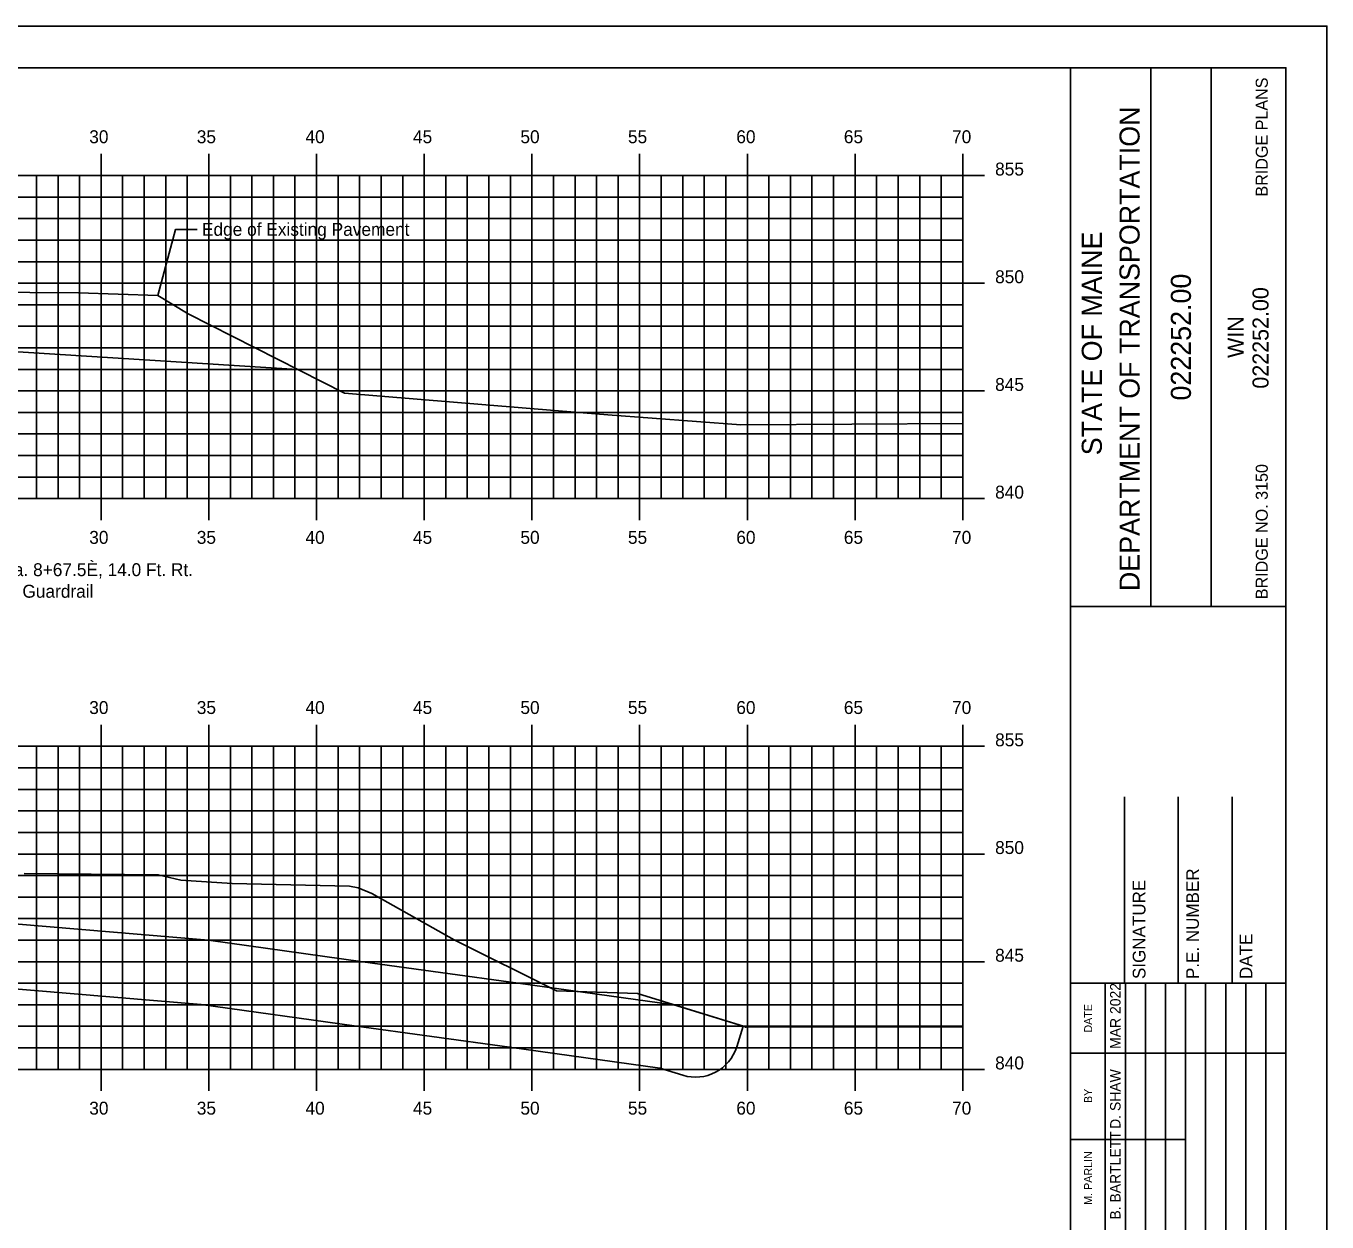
# Model space of a CAD drawing. Extents: x 2194256 to 2194747, y 863888 to 863998.
# Drawn here: x 2194503.3 to 2194563.6, y 863942.9 to 863998.4 of the extents above; entities that cross this region are included whole.
import ezdxf

# ---------------------------------------------------------------- set-up
doc = ezdxf.new("R2010")
doc.units = 0
for name, color, linetype in [('ANNOTATION', 7, 'Continuous'), ('BORDER', 7, 'Continuous'), ('BRIDGE_TITLE', 7, 'Continuous'), ('H_V ANNOTATION', 7, 'Continuous'), ('MAJOR', 7, 'Continuous'), ('MINOR', 7, 'Continuous'), ('Patterning', 7, 'Continuous'), ('PLOT BOUNDARY', 7, 'Continuous'), ('S_Roadway_Centerline', 7, 'Continuous'), ('TEMPLATE', 7, 'Continuous')]:
    doc.layers.add(name, color=color, linetype=linetype)

msp = doc.modelspace()

# ---------------------------------------------------------------- linework, layer by layer
at = {"layer": 'ANNOTATION'}
msp.add_lwpolyline([(2194511.197, 863988.946), (2194510.197, 863988.946), (2194509.373, 863985.868)], dxfattribs=at)
at = {"layer": 'BORDER'}
for p, q in [((2194551.743, 863891.446), (2194551.743, 863996.446)), ((2194555.472, 863971.443), (2194555.472, 863996.443)), ((2194558.267, 863971.443), (2194558.267, 863996.443)), ((2194551.744, 863971.44), (2194561.743, 863971.44)), ((2194554.243, 863953.949), (2194554.243, 863962.596)), ((2194556.743, 863953.949), (2194556.743, 863962.596)), ((2194559.243, 863953.949), (2194559.243, 863962.596)), ((2194551.743, 863953.949), (2194561.743, 863953.949))]:
    msp.add_line(p, q, dxfattribs=at)
msp.add_lwpolyline([(2194401.743, 863891.446), (2194561.743, 863891.446), (2194561.743, 863996.446), (2194401.743, 863996.446)], close=True, dxfattribs=at)
for points in [[(2194553.358, 863950.699), (2194553.358, 863953.949)], [(2194554.29, 863936.452), (2194554.29, 863953.949)], [(2194555.222, 863953.949), (2194555.222, 863936.452)], [(2194556.154, 863936.452), (2194556.154, 863953.949)], [(2194557.085, 863936.452), (2194557.085, 863953.949)], [(2194558.017, 863936.452), (2194558.017, 863953.949)], [(2194558.949, 863936.452), (2194558.949, 863953.949)], [(2194559.881, 863936.452), (2194559.881, 863953.949)], [(2194560.812, 863936.452), (2194560.812, 863953.949)], [(2194553.359, 863936.452), (2194553.359, 863953.243)], [(2194551.743, 863950.699), (2194561.743, 863950.699)], [(2194551.743, 863946.699), (2194553.359, 863946.699)], [(2194553.358, 863946.699), (2194557.085, 863946.699)]]:
    msp.add_lwpolyline(points, dxfattribs=at)
at = {"layer": 'MAJOR'}
for p, q in [((2194506.743, 863992.448), (2194506.743, 863991.446)), ((2194511.743, 863992.448), (2194511.743, 863991.446)), ((2194516.743, 863992.448), (2194516.743, 863991.446)), ((2194521.743, 863992.448), (2194521.743, 863991.446)), ((2194526.743, 863992.448), (2194526.743, 863991.446)), ((2194531.743, 863992.448), (2194531.743, 863991.446)), ((2194536.743, 863992.448), (2194536.743, 863991.446)), ((2194541.743, 863992.448), (2194541.743, 863991.446)), ((2194546.743, 863992.448), (2194546.743, 863991.446)), ((2194406.743, 863991.446), (2194546.743, 863991.446)), ((2194506.743, 863976.446), (2194506.743, 863991.446)), ((2194511.743, 863976.446), (2194511.743, 863991.446)), ((2194516.743, 863976.446), (2194516.743, 863991.446)), ((2194521.743, 863976.446), (2194521.743, 863991.446)), ((2194526.743, 863976.446), (2194526.743, 863991.446)), ((2194531.743, 863976.446), (2194531.743, 863991.446)), ((2194536.743, 863976.446), (2194536.743, 863991.446)), ((2194541.743, 863976.446), (2194541.743, 863991.446)), ((2194547.745, 863991.446), (2194545.741, 863991.446)), ((2194546.743, 863976.446), (2194546.743, 863991.446)), ((2194546.743, 863976.446), (2194546.743, 863991.446)), ((2194406.743, 863986.446), (2194546.743, 863986.446)), ((2194547.745, 863986.446), (2194545.741, 863986.446)), ((2194406.743, 863981.446), (2194546.743, 863981.446)), ((2194547.745, 863981.446), (2194545.741, 863981.446)), ((2194406.743, 863976.446), (2194546.743, 863976.446)), ((2194506.743, 863975.444), (2194506.743, 863976.446)), ((2194511.743, 863975.444), (2194511.743, 863976.446)), ((2194516.743, 863975.444), (2194516.743, 863976.446)), ((2194521.743, 863975.444), (2194521.743, 863976.446)), ((2194526.743, 863975.444), (2194526.743, 863976.446)), ((2194531.743, 863975.444), (2194531.743, 863976.446)), ((2194536.743, 863975.444), (2194536.743, 863976.446)), ((2194541.743, 863975.444), (2194541.743, 863976.446)), ((2194547.745, 863976.446), (2194545.741, 863976.446)), ((2194546.743, 863975.444), (2194546.743, 863976.446)), ((2194506.743, 863965.948), (2194506.743, 863964.946)), ((2194511.743, 863965.948), (2194511.743, 863964.946)), ((2194516.743, 863965.948), (2194516.743, 863964.946)), ((2194521.743, 863965.948), (2194521.743, 863964.946)), ((2194526.743, 863965.948), (2194526.743, 863964.946)), ((2194531.743, 863965.948), (2194531.743, 863964.946)), ((2194536.743, 863965.948), (2194536.743, 863964.946)), ((2194541.743, 863965.948), (2194541.743, 863964.946)), ((2194546.743, 863965.948), (2194546.743, 863964.946)), ((2194406.743, 863964.946), (2194546.743, 863964.946)), ((2194406.743, 863964.946), (2194546.743, 863964.946)), ((2194506.743, 863949.946), (2194506.743, 863964.946)), ((2194511.743, 863949.946), (2194511.743, 863964.946)), ((2194516.743, 863949.946), (2194516.743, 863964.946)), ((2194521.743, 863949.946), (2194521.743, 863964.946)), ((2194526.743, 863949.946), (2194526.743, 863964.946)), ((2194531.743, 863949.946), (2194531.743, 863964.946)), ((2194536.743, 863949.946), (2194536.743, 863964.946)), ((2194541.743, 863949.946), (2194541.743, 863964.946)), ((2194547.745, 863964.946), (2194545.741, 863964.946)), ((2194546.743, 863949.946), (2194546.743, 863964.946)), ((2194546.743, 863949.946), (2194546.743, 863964.946)), ((2194406.743, 863959.946), (2194546.743, 863959.946)), ((2194547.745, 863959.946), (2194545.741, 863959.946)), ((2194406.743, 863954.946), (2194546.743, 863954.946)), ((2194547.745, 863954.946), (2194545.741, 863954.946)), ((2194406.743, 863949.946), (2194546.743, 863949.946)), ((2194506.743, 863948.944), (2194506.743, 863949.946)), ((2194511.743, 863948.944), (2194511.743, 863949.946)), ((2194516.743, 863948.944), (2194516.743, 863949.946)), ((2194521.743, 863948.944), (2194521.743, 863949.946)), ((2194526.743, 863948.944), (2194526.743, 863949.946)), ((2194531.743, 863948.944), (2194531.743, 863949.946)), ((2194536.743, 863948.944), (2194536.743, 863949.946)), ((2194541.743, 863948.944), (2194541.743, 863949.946)), ((2194547.745, 863949.946), (2194545.741, 863949.946)), ((2194546.743, 863948.944), (2194546.743, 863949.946))]:
    msp.add_line(p, q, dxfattribs=at)
at = {"layer": 'MINOR'}
for p, q in [((2194503.743, 863976.446), (2194503.743, 863991.446)), ((2194504.743, 863976.446), (2194504.743, 863991.446)), ((2194505.743, 863976.446), (2194505.743, 863991.446)), ((2194507.743, 863976.446), (2194507.743, 863991.446)), ((2194508.743, 863976.446), (2194508.743, 863991.446)), ((2194509.743, 863976.446), (2194509.743, 863991.446)), ((2194510.743, 863976.446), (2194510.743, 863991.446)), ((2194512.743, 863976.446), (2194512.743, 863991.446)), ((2194513.743, 863976.446), (2194513.743, 863991.446)), ((2194514.743, 863976.446), (2194514.743, 863991.446)), ((2194515.743, 863976.446), (2194515.743, 863991.446)), ((2194517.743, 863976.446), (2194517.743, 863991.446)), ((2194518.743, 863976.446), (2194518.743, 863991.446)), ((2194519.743, 863976.446), (2194519.743, 863991.446)), ((2194520.743, 863976.446), (2194520.743, 863991.446)), ((2194522.743, 863976.446), (2194522.743, 863991.446)), ((2194523.743, 863976.446), (2194523.743, 863991.446)), ((2194524.743, 863976.446), (2194524.743, 863991.446)), ((2194525.743, 863976.446), (2194525.743, 863991.446)), ((2194527.743, 863976.446), (2194527.743, 863991.446)), ((2194528.743, 863976.446), (2194528.743, 863991.446)), ((2194529.743, 863976.446), (2194529.743, 863991.446)), ((2194530.743, 863976.446), (2194530.743, 863991.446)), ((2194532.743, 863976.446), (2194532.743, 863991.446)), ((2194533.743, 863976.446), (2194533.743, 863991.446)), ((2194534.743, 863976.446), (2194534.743, 863991.446)), ((2194535.743, 863976.446), (2194535.743, 863991.446)), ((2194537.743, 863976.446), (2194537.743, 863991.446)), ((2194538.743, 863976.446), (2194538.743, 863991.446)), ((2194539.743, 863976.446), (2194539.743, 863991.446)), ((2194540.743, 863976.446), (2194540.743, 863991.446)), ((2194542.743, 863976.446), (2194542.743, 863991.446)), ((2194543.743, 863976.446), (2194543.743, 863991.446)), ((2194544.743, 863976.446), (2194544.743, 863991.446)), ((2194545.743, 863976.446), (2194545.743, 863991.446)), ((2194406.743, 863990.446), (2194546.743, 863990.446)), ((2194546.743, 863990.446), (2194545.741, 863990.446)), ((2194406.743, 863989.446), (2194546.743, 863989.446)), ((2194546.743, 863989.446), (2194545.741, 863989.446)), ((2194406.743, 863988.446), (2194546.743, 863988.446)), ((2194546.743, 863988.446), (2194545.741, 863988.446)), ((2194406.743, 863987.446), (2194546.743, 863987.446)), ((2194546.743, 863987.446), (2194545.741, 863987.446)), ((2194406.743, 863985.446), (2194546.743, 863985.446)), ((2194546.743, 863985.446), (2194545.741, 863985.446)), ((2194406.743, 863984.446), (2194546.743, 863984.446)), ((2194546.743, 863984.446), (2194545.741, 863984.446)), ((2194406.743, 863983.446), (2194546.743, 863983.446)), ((2194546.743, 863983.446), (2194545.741, 863983.446)), ((2194406.743, 863982.446), (2194546.743, 863982.446)), ((2194546.743, 863982.446), (2194545.741, 863982.446)), ((2194406.743, 863980.446), (2194546.743, 863980.446)), ((2194546.743, 863980.446), (2194545.741, 863980.446)), ((2194406.743, 863979.446), (2194546.743, 863979.446)), ((2194546.743, 863979.446), (2194545.741, 863979.446)), ((2194406.743, 863978.446), (2194546.743, 863978.446)), ((2194546.743, 863978.446), (2194545.741, 863978.446)), ((2194406.743, 863977.446), (2194546.743, 863977.446)), ((2194546.743, 863977.446), (2194545.741, 863977.446)), ((2194503.743, 863949.946), (2194503.743, 863964.946)), ((2194504.743, 863949.946), (2194504.743, 863964.946)), ((2194505.743, 863949.946), (2194505.743, 863964.946)), ((2194507.743, 863949.946), (2194507.743, 863964.946)), ((2194508.743, 863949.946), (2194508.743, 863964.946)), ((2194509.743, 863949.946), (2194509.743, 863964.946)), ((2194510.743, 863949.946), (2194510.743, 863964.946)), ((2194512.743, 863949.946), (2194512.743, 863964.946)), ((2194513.743, 863949.946), (2194513.743, 863964.946)), ((2194514.743, 863949.946), (2194514.743, 863964.946)), ((2194515.743, 863949.946), (2194515.743, 863964.946)), ((2194517.743, 863949.946), (2194517.743, 863964.946)), ((2194518.743, 863949.946), (2194518.743, 863964.946)), ((2194519.743, 863949.946), (2194519.743, 863964.946)), ((2194520.743, 863949.946), (2194520.743, 863964.946)), ((2194522.743, 863949.946), (2194522.743, 863964.946)), ((2194523.743, 863949.946), (2194523.743, 863964.946)), ((2194524.743, 863949.946), (2194524.743, 863964.946)), ((2194525.743, 863949.946), (2194525.743, 863964.946)), ((2194527.743, 863949.946), (2194527.743, 863964.946)), ((2194528.743, 863949.946), (2194528.743, 863964.946)), ((2194529.743, 863949.946), (2194529.743, 863964.946)), ((2194530.743, 863949.946), (2194530.743, 863964.946)), ((2194532.743, 863949.946), (2194532.743, 863964.946)), ((2194533.743, 863949.946), (2194533.743, 863964.946)), ((2194534.743, 863949.946), (2194534.743, 863964.946)), ((2194535.743, 863949.946), (2194535.743, 863964.946)), ((2194537.743, 863949.946), (2194537.743, 863964.946)), ((2194538.743, 863949.946), (2194538.743, 863964.946)), ((2194539.743, 863949.946), (2194539.743, 863964.946)), ((2194540.743, 863949.946), (2194540.743, 863964.946)), ((2194542.743, 863949.946), (2194542.743, 863964.946)), ((2194543.743, 863949.946), (2194543.743, 863964.946)), ((2194544.743, 863949.946), (2194544.743, 863964.946)), ((2194545.743, 863949.946), (2194545.743, 863964.946)), ((2194406.743, 863963.946), (2194546.743, 863963.946)), ((2194546.743, 863963.946), (2194545.741, 863963.946)), ((2194406.743, 863962.946), (2194546.743, 863962.946)), ((2194546.743, 863962.946), (2194545.741, 863962.946)), ((2194406.743, 863961.946), (2194546.743, 863961.946)), ((2194546.743, 863961.946), (2194545.741, 863961.946)), ((2194406.743, 863960.946), (2194546.743, 863960.946)), ((2194546.743, 863960.946), (2194545.741, 863960.946)), ((2194406.743, 863958.946), (2194546.743, 863958.946)), ((2194546.743, 863958.946), (2194545.741, 863958.946)), ((2194406.743, 863957.946), (2194546.743, 863957.946)), ((2194546.743, 863957.946), (2194545.741, 863957.946)), ((2194406.743, 863956.946), (2194546.743, 863956.946)), ((2194546.743, 863956.946), (2194545.741, 863956.946)), ((2194406.743, 863955.946), (2194546.743, 863955.946)), ((2194546.743, 863955.946), (2194545.741, 863955.946)), ((2194406.743, 863953.946), (2194546.743, 863953.946)), ((2194546.743, 863953.946), (2194545.741, 863953.946)), ((2194406.743, 863952.946), (2194546.743, 863952.946)), ((2194546.743, 863952.946), (2194545.741, 863952.946)), ((2194406.743, 863951.946), (2194546.743, 863951.946)), ((2194546.743, 863951.946), (2194545.741, 863951.946)), ((2194406.743, 863950.946), (2194546.743, 863950.946)), ((2194546.743, 863950.946), (2194545.741, 863950.946))]:
    msp.add_line(p, q, dxfattribs=at)
at = {"layer": 'Patterning'}
msp.add_line((2194536.248, 863950.991), (2194536.545, 863951.946), dxfattribs=at)
for points in [[(2194536.545, 863951.946), (2194533.328, 863952.946), (2194526.106, 863953.946), (2194518.899, 863954.946), (2194511.723, 863955.946), (2194499.763, 863956.946), (2194499.4, 863957.127)], [(2194499.4, 863953.966), (2194511.39, 863952.963), (2194518.486, 863951.974), (2194525.694, 863950.974), (2194532.672, 863950.008), (2194533.744, 863949.675)]]:
    msp.add_lwpolyline(points, dxfattribs=at)
msp.add_arc((2194534.338, 863951.584), 2, 252.73222, 342.73222, dxfattribs=at)
at = {"layer": 'PLOT BOUNDARY'}
msp.add_lwpolyline([(2194393.65, 863888.387), (2194563.65, 863888.387), (2194563.65, 863998.387), (2194393.65, 863998.387)], close=True, dxfattribs=at)
at = {"layer": 'S_Roadway_Centerline'}
for points in [[(2194498.885, 863986.051), (2194505.695, 863985.992), (2194509.373, 863985.868), (2194510.789, 863985.022), (2194518.04, 863981.342), (2194527.981, 863980.527), (2194530.267, 863980.336), (2194536.441, 863979.867), (2194546.743, 863979.939)], [(2194503.173, 863959.04), (2194509.394, 863958.986), (2194510.449, 863958.73), (2194512.834, 863958.58), (2194518.275, 863958.447), (2194518.682, 863958.368), (2194519.303, 863958.11), (2194523.131, 863955.956), (2194527.875, 863953.591), (2194531.648, 863953.466), (2194536.604, 863951.93), (2194536.658, 863951.91), (2194536.685, 863951.91), (2194546.743, 863951.928)], [(2194533.744, 863949.675), (2194532.672, 863950.008), (2194525.694, 863950.974), (2194518.486, 863951.974), (2194511.39, 863952.963), (2194499.4, 863953.966)], [(2194536.545, 863951.948), (2194536.248, 863950.991)]]:
    msp.add_lwpolyline(points, dxfattribs=at)
msp.add_arc((2194534.338, 863951.584), 2, 252.73222, 342.73222, dxfattribs=at)
at = {"layer": 'TEMPLATE'}
msp.add_line((2194515.866, 863982.446), (2194499.943, 863983.446), dxfattribs=at)
msp.add_lwpolyline([(2194536.545, 863951.946), (2194533.328, 863952.946), (2194526.106, 863953.946), (2194518.899, 863954.946), (2194511.723, 863955.946), (2194499.763, 863956.946), (2194493.743, 863959.956)], dxfattribs=at)

# ---------------------------------------------------------------- texts
at = {"layer": 'ANNOTATION'}
for s, p in [('Edge of Existing Pavement', (2194511.423, 863988.646)), ('Sta. 8+45.6È, 14.0 Ft. Rt. to Sta. 8+67.5È, 14.0 Ft. Rt.', (2194491.743, 863972.846)), ('Install 21.9 L.F. of 31" W-Beam Guardrail', (2194491.743, 863971.844))]:
    msp.add_text(s, height=0.6, dxfattribs=at).set_placement(p)
at = {"layer": 'BORDER'}
for s, height, p in [('DEPARTMENT OF TRANSPORTATION', 0.93176, (2194554.95, 863972.152)), ('STATE OF MAINE', 0.93176, (2194553.198, 863978.458)), ('022252.00', 0.9318, (2194557.335, 863980.999)), ('022252.00', 0.7453, (2194560.938, 863981.551)), ('WIN', 0.7453, (2194559.78, 863982.976)), ('P.E. NUMBER', 0.59055, (2194557.704, 863954.141)), ('SIGNATURE', 0.5906, (2194555.223, 863954.141)), ('DATE', 0.5906, (2194560.184, 863954.141)), ('MAR 2022', 0.4845, (2194554.066, 863950.897)), ('DATE', 0.3714, (2194552.747, 863951.654)), ('D. SHAW', 0.4845, (2194554.066, 863947.184)), ('BY', 0.3714, (2194552.747, 863948.384)), ('B. BARTLETT', 0.48455, (2194554.066, 863942.972)), ('M. PARLIN', 0.3727, (2194552.747, 863943.656))]:
    msp.add_text(s, height=height, rotation=90, dxfattribs=at).set_placement(p)
at = {"layer": 'BRIDGE_TITLE'}
for s, p in [('BRIDGE PLANS', (2194560.901, 863990.47)), ('BRIDGE NO. 3150', (2194560.901, 863971.776))]:
    msp.add_text(s, height=0.55901, rotation=90, dxfattribs=at).set_placement(p)
at = {"layer": 'H_V ANNOTATION'}
for s, p in [('30', (2194506.191, 863992.946)), ('35', (2194511.183, 863992.946)), ('40', (2194516.229, 863992.946)), ('45', (2194521.221, 863992.946)), ('50', (2194526.207, 863992.946)), ('55', (2194531.199, 863992.946)), ('60', (2194536.229, 863992.946)), ('65', (2194541.221, 863992.946)), ('70', (2194546.245, 863992.946)), ('855', (2194548.243, 863991.446)), ('850', (2194548.243, 863986.446)), ('845', (2194548.243, 863981.446)), ('840', (2194548.243, 863976.446)), ('30', (2194506.191, 863974.346)), ('35', (2194511.183, 863974.346)), ('40', (2194516.229, 863974.346)), ('45', (2194521.221, 863974.346)), ('50', (2194526.207, 863974.346)), ('55', (2194531.199, 863974.346)), ('60', (2194536.229, 863974.346)), ('65', (2194541.221, 863974.346)), ('70', (2194546.245, 863974.346)), ('30', (2194506.191, 863966.446)), ('35', (2194511.183, 863966.446)), ('40', (2194516.229, 863966.446)), ('45', (2194521.221, 863966.446)), ('50', (2194526.207, 863966.446)), ('55', (2194531.199, 863966.446)), ('60', (2194536.229, 863966.446)), ('65', (2194541.221, 863966.446)), ('70', (2194546.245, 863966.446)), ('855', (2194548.243, 863964.946)), ('850', (2194548.243, 863959.946)), ('845', (2194548.243, 863954.946)), ('840', (2194548.243, 863949.946)), ('30', (2194506.191, 863947.846)), ('35', (2194511.183, 863947.846)), ('40', (2194516.229, 863947.846)), ('45', (2194521.221, 863947.846)), ('50', (2194526.207, 863947.846)), ('55', (2194531.199, 863947.846)), ('60', (2194536.229, 863947.846)), ('65', (2194541.221, 863947.846)), ('70', (2194546.245, 863947.846))]:
    msp.add_text(s, height=0.6, dxfattribs=at).set_placement(p)

doc.saveas('drawing.dxf')
